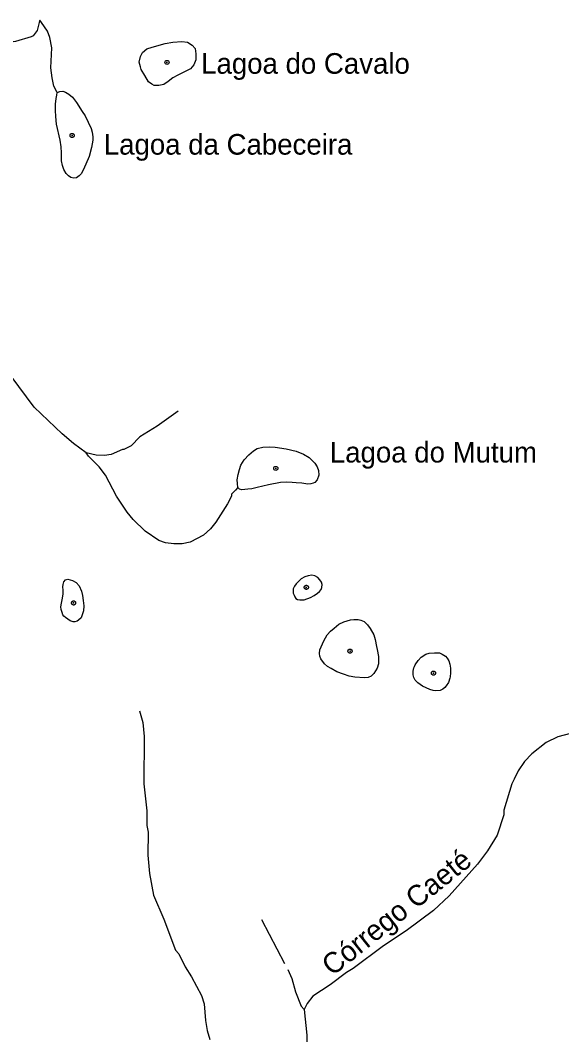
# Model space of a CAD drawing. Extents: x 393 to 446.6, y 8175.5 to 8231.
# Drawn here: x 420.3 to 424.5, y 8223.04 to 8230.9 of the extents above; entities that cross this region are included whole.
import ezdxf
from ezdxf.enums import TextEntityAlignment as Align

# ---------------------------------------------------------------- set-up
doc = ezdxf.new("R2010")
doc.units = 0
doc.header["$LTSCALE"] = 0.064
doc.header["$PDMODE"] = 32
doc.header["$PDSIZE"] = 0.032
doc.linetypes.add('LONG_DASHED', pattern=[7.5, 6, -1.5])
for name, color, linetype, lineweight in [('2', 7, 'Continuous', 25), ('3', 7, 'LONG_DASHED', 25), ('7', 7, 'Continuous', 25), ('9', 7, 'LONG_DASHED', 25)]:
    doc.layers.add(name, color=color, linetype=linetype, lineweight=lineweight)
doc.layers.add('61', color=7, linetype='Continuous')

msp = doc.modelspace()

# ---------------------------------------------------------------- linework, layer by layer
at = {"layer": '2'}
for points in [[(421.2704, 8230.4736), (421.2426, 8230.5206), (421.2361, 8230.5399), (421.2276, 8230.5763), (421.2361, 8230.6212), (421.2533, 8230.6512), (421.2854, 8230.679), (421.326, 8230.694), (421.4288, 8230.7218), (421.4865, 8230.7304), (421.5572, 8230.7368), (421.6021, 8230.7304), (421.6385, 8230.709), (421.6599, 8230.6812), (421.6663, 8230.6405), (421.6663, 8230.5934), (421.6492, 8230.5549), (421.6256, 8230.5249), (421.5828, 8230.5035), (421.5272, 8230.4757), (421.4887, 8230.4543), (421.4502, 8230.4265), (421.418, 8230.4029), (421.3792, 8230.3966), (421.3433, 8230.3954), (421.3239, 8230.4051), (421.2982, 8230.4243)], [(421.9913, 8227.2798), (421.9883, 8227.3094), (421.9868, 8227.339), (421.9942, 8227.3805), (422.0031, 8227.4189), (422.015, 8227.4515), (422.0401, 8227.4944), (422.0756, 8227.5329), (422.1141, 8227.564), (422.1408, 8227.5803), (422.1852, 8227.5906), (422.2355, 8227.5936), (422.2799, 8227.5906), (422.3657, 8227.5788), (422.4442, 8227.5596), (422.5004, 8227.5373), (422.5448, 8227.5107), (422.5878, 8227.4678), (422.607, 8227.4397), (422.6159, 8227.4115), (422.6188, 8227.3745), (422.607, 8227.339), (422.5878, 8227.3183), (422.5744, 8227.3124), (422.5567, 8227.3065), (422.533, 8227.305), (422.4871, 8227.3124), (422.4442, 8227.3153), (422.4116, 8227.3183), (422.3717, 8227.3198), (422.3213, 8227.3168), (422.2281, 8227.2991), (422.1422, 8227.2783), (422.1008, 8227.2695), (422.0697, 8227.265), (422.0446, 8227.2621), (422.0224, 8227.2606), (422.0031, 8227.2665)]]:
    msp.add_lwpolyline(points, close=True, dxfattribs=at)
for p in [(421.4418, 8230.5747), (422.2855, 8227.4268)]:
    msp.add_point(p, dxfattribs=at)
at = {"layer": '3'}
for points in [[(420.5901, 8230.3421), (420.612, 8230.3479), (420.6338, 8230.3508), (420.6556, 8230.345), (420.6818, 8230.329), (420.7095, 8230.3042), (420.7401, 8230.2635), (420.7852, 8230.1951), (420.807, 8230.1601), (420.8303, 8230.1106), (420.8536, 8230.0611), (420.8609, 8230.0335), (420.8682, 8229.9985), (420.8682, 8229.9709), (420.8565, 8229.9156), (420.8376, 8229.8442), (420.7939, 8229.7438), (420.7765, 8229.7103), (420.7619, 8229.6943), (420.7415, 8229.6797), (420.7197, 8229.6768), (420.6978, 8229.6826), (420.6775, 8229.6943), (420.66, 8229.7132), (420.6411, 8229.7438), (420.6323, 8229.7744), (420.6251, 8229.8122), (420.6236, 8229.8733), (420.6221, 8229.9199), (420.6134, 8229.9723), (420.5843, 8230.0961), (420.5799, 8230.1558), (420.5785, 8230.2009), (420.577, 8230.2504), (420.5828, 8230.294), (420.5887, 8230.3217)], [(420.6559, 8226.2713), (420.6428, 8226.2807), (420.6353, 8226.2919), (420.6287, 8226.3097), (420.6222, 8226.3331), (420.6203, 8226.3537), (420.6231, 8226.3808), (420.6297, 8226.407), (420.6371, 8226.4529), (420.6371, 8226.4819), (420.6343, 8226.509), (420.6362, 8226.5278), (420.6428, 8226.5483), (420.6559, 8226.5633), (420.6746, 8226.568), (420.7083, 8226.5586), (420.7392, 8226.5418), (420.7607, 8226.5165), (420.7785, 8226.4744), (420.7878, 8226.4417), (420.7934, 8226.4033), (420.7962, 8226.3602), (420.7944, 8226.3219), (420.7775, 8226.2685), (420.7569, 8226.2498), (420.7457, 8226.2414), (420.7289, 8226.2367), (420.7148, 8226.2376), (420.6914, 8226.2442)], [(422.4193, 8226.4764), (422.4211, 8226.4594), (422.4269, 8226.4435), (422.4334, 8226.43), (422.4416, 8226.4189), (422.4533, 8226.4107), (422.4715, 8226.4066), (422.5055, 8226.4077), (422.5548, 8226.4253), (422.5841, 8226.4423), (422.6082, 8226.4594), (422.624, 8226.4717), (422.6381, 8226.4881), (422.6434, 8226.5028), (422.6451, 8226.5256), (422.641, 8226.5438), (422.6281, 8226.5638), (422.6123, 8226.5814), (422.5888, 8226.5943), (422.5653, 8226.5978), (422.5354, 8226.5948), (422.5096, 8226.5855), (422.4826, 8226.5702), (422.4633, 8226.5538), (422.4439, 8226.5321), (422.4316, 8226.5139), (422.4211, 8226.494)], [(422.6586, 8226.0897), (422.6842, 8226.1369), (422.7097, 8226.165), (422.7377, 8226.1892), (422.7747, 8226.2186), (422.813, 8226.2377), (422.864, 8226.253), (422.8895, 8226.2543), (422.9068, 8226.2543), (422.924, 8226.2543), (422.9457, 8226.2505), (422.9699, 8226.239), (422.9954, 8226.2135), (423.0171, 8226.1854), (423.0465, 8226.1369), (423.0554, 8226.1012), (423.0669, 8226.0463), (423.0712, 8226.0224), (423.0809, 8225.9685), (423.0809, 8225.9111), (423.0707, 8225.8792), (423.0592, 8225.8575), (423.0452, 8225.8358), (423.026, 8225.8154), (423.0018, 8225.8052), (422.9725, 8225.8027), (422.8985, 8225.8078), (422.8538, 8225.8167), (422.8117, 8225.8307), (422.7581, 8225.8499), (422.7148, 8225.8754), (422.6867, 8225.892), (422.6637, 8225.9124), (422.6357, 8225.9494), (422.628, 8225.9711), (422.6242, 8225.9915), (422.628, 8226.0208)], [(423.3864, 8225.765), (423.3666, 8225.7848), (423.3567, 8225.8045), (423.3518, 8225.8262), (423.3508, 8225.8539), (423.3548, 8225.8796), (423.3607, 8225.8919), (423.3666, 8225.9043), (423.3903, 8225.9379), (423.413, 8225.9626), (423.4486, 8225.9863), (423.4753, 8225.9932), (423.5158, 8225.9981), (423.5543, 8225.9961), (423.576, 8225.9873), (423.6007, 8225.9715), (423.6136, 8225.9556), (423.6264, 8225.9339), (423.6353, 8225.9082), (423.6412, 8225.8776), (423.6402, 8225.8411), (423.6365, 8225.8107), (423.6353, 8225.8006), (423.6234, 8225.768), (423.6076, 8225.7423), (423.5958, 8225.7275), (423.582, 8225.7146), (423.5602, 8225.7038), (423.5237, 8225.7018), (423.5069, 8225.7038), (423.4802, 8225.7126), (423.4239, 8225.7373)]]:
    msp.add_lwpolyline(points, close=True, dxfattribs=at)
for p in [(420.7063, 8230.0083), (422.5223, 8226.5047), (420.718, 8226.3836), (422.8611, 8226.0104), (423.5082, 8225.8397)]:
    msp.add_point(p, dxfattribs=at)
at = {"layer": '7'}
for points in [[(420.4564, 8230.9012), (420.4523, 8230.8851), (420.4365, 8230.823), (420.4058, 8230.781), (420.3881, 8230.7729), (420.2686, 8230.7357), (420.1653, 8230.7212), (420.0619, 8230.718), (420.0118, 8230.705), (419.9295, 8230.6566), (419.7906, 8230.6017), (419.6372, 8230.5597), (419.5484, 8230.5048), (419.5209, 8230.4855), (419.4644, 8230.4096), (419.4525, 8230.3719), (419.445, 8230.3482), (419.4457, 8230.2275)], [(420.5901, 8230.3421), (420.5874, 8230.3475), (420.5657, 8230.3902), (420.5512, 8230.4548), (420.5415, 8230.5323), (420.5496, 8230.6873), (420.535, 8230.7681), (420.5156, 8230.8165), (420.4699, 8230.8851), (420.4564, 8230.9012)], [(420.8158, 8227.5472), (420.7184, 8227.6189), (420.6287, 8227.6951), (420.4123, 8227.9018), (420.2347, 8228.1424), (420.057, 8228.4137), (420.0296, 8228.446), (419.9973, 8228.4766), (419.9295, 8228.5218), (419.8257, 8228.547)], [(421.5295, 8227.8703), (421.3667, 8227.7548), (421.231, 8227.6725), (421.1632, 8227.6014), (421.1083, 8227.5723), (421.097, 8227.5723), (421.0082, 8227.5336), (420.9565, 8227.5271), (420.8935, 8227.5304), (420.8158, 8227.5472)], [(421.9913, 8227.2798), (421.9726, 8227.2593), (421.9431, 8227.2268), (421.9415, 8227.2107), (421.9108, 8227.1509), (421.8204, 8227.0088), (421.78, 8226.9587), (421.7251, 8226.9103), (421.6218, 8226.8554), (421.5604, 8226.8425), (421.4958, 8226.8409), (421.4313, 8226.8489), (421.3796, 8226.8683), (421.273, 8226.9393), (421.1793, 8227.0314), (421.1325, 8227.0863), (421.0501, 8227.2107), (420.9645, 8227.3738), (420.9161, 8227.4384), (420.8338, 8227.5207), (420.8158, 8227.5472)], [(421.2295, 8225.5461), (421.2539, 8225.4577), (421.2644, 8225.3483), (421.2632, 8224.9817), (421.2859, 8224.7707), (421.2859, 8224.6577), (421.2956, 8224.606), (421.2924, 8224.4284), (421.3053, 8224.2863), (421.3376, 8224.1183), (421.4183, 8223.931), (421.5087, 8223.692), (421.5329, 8223.6629), (421.583, 8223.5628), (421.6315, 8223.4853), (421.709, 8223.34), (421.73, 8223.2754), (421.7413, 8223.1462), (421.7542, 8223.0687), (421.7752, 8222.9977)]]:
    msp.add_lwpolyline(points, dxfattribs=at)
at = {"layer": '9'}
for points in [[(424.5703, 8225.372), (424.4726, 8225.3458), (424.3825, 8225.3015), (424.2696, 8225.2142), (424.2151, 8225.1534), (424.165, 8225.0822), (424.1343, 8225.0186), (424.1166, 8224.982), (424.054, 8224.7777), (424.0535, 8224.7398), (424.0013, 8224.5842), (423.9259, 8224.4607), (423.8502, 8224.3589), (423.6288, 8224.1135), (423.5075, 8224.0003), (423.2973, 8223.8403), (423.1217, 8223.7241), (422.8844, 8223.5499), (422.833, 8223.5191), (422.7068, 8223.4223), (422.574, 8223.3342), (422.529, 8223.2771), (422.5046, 8223.2305)], [(422.1759, 8223.9295), (422.3791, 8223.5419), (422.4101, 8223.4714), (422.4394, 8223.3674), (422.4829, 8223.2568), (422.5046, 8223.2305)], [(422.5046, 8223.2305), (422.526, 8223.0331), (422.5259, 8222.9312), (422.4782, 8222.7335), (422.4711, 8222.7039), (422.4449, 8222.6379), (422.4368, 8222.5978), (422.3781, 8222.4691), (422.3735, 8222.4472), (422.3723, 8222.4414)]]:
    msp.add_lwpolyline(points, dxfattribs=at)

# ---------------------------------------------------------------- texts
at = {"layer": '61'}
for s, p in [('Lagoa do Cavalo', (421.7071, 8230.4866)), ('Lagoa da Cabeceira', (420.9523, 8229.8595)), ('Lagoa do Mutum', (422.7049, 8227.4723))]:
    msp.add_text(s, height=0.16, dxfattribs=at).set_placement(p)
msp.add_text('Córrego Caeté', height=0.16, rotation=38.701, dxfattribs=at).set_placement((423.271, 8223.9239), align=Align.CENTER)

doc.saveas('drawing.dxf')
